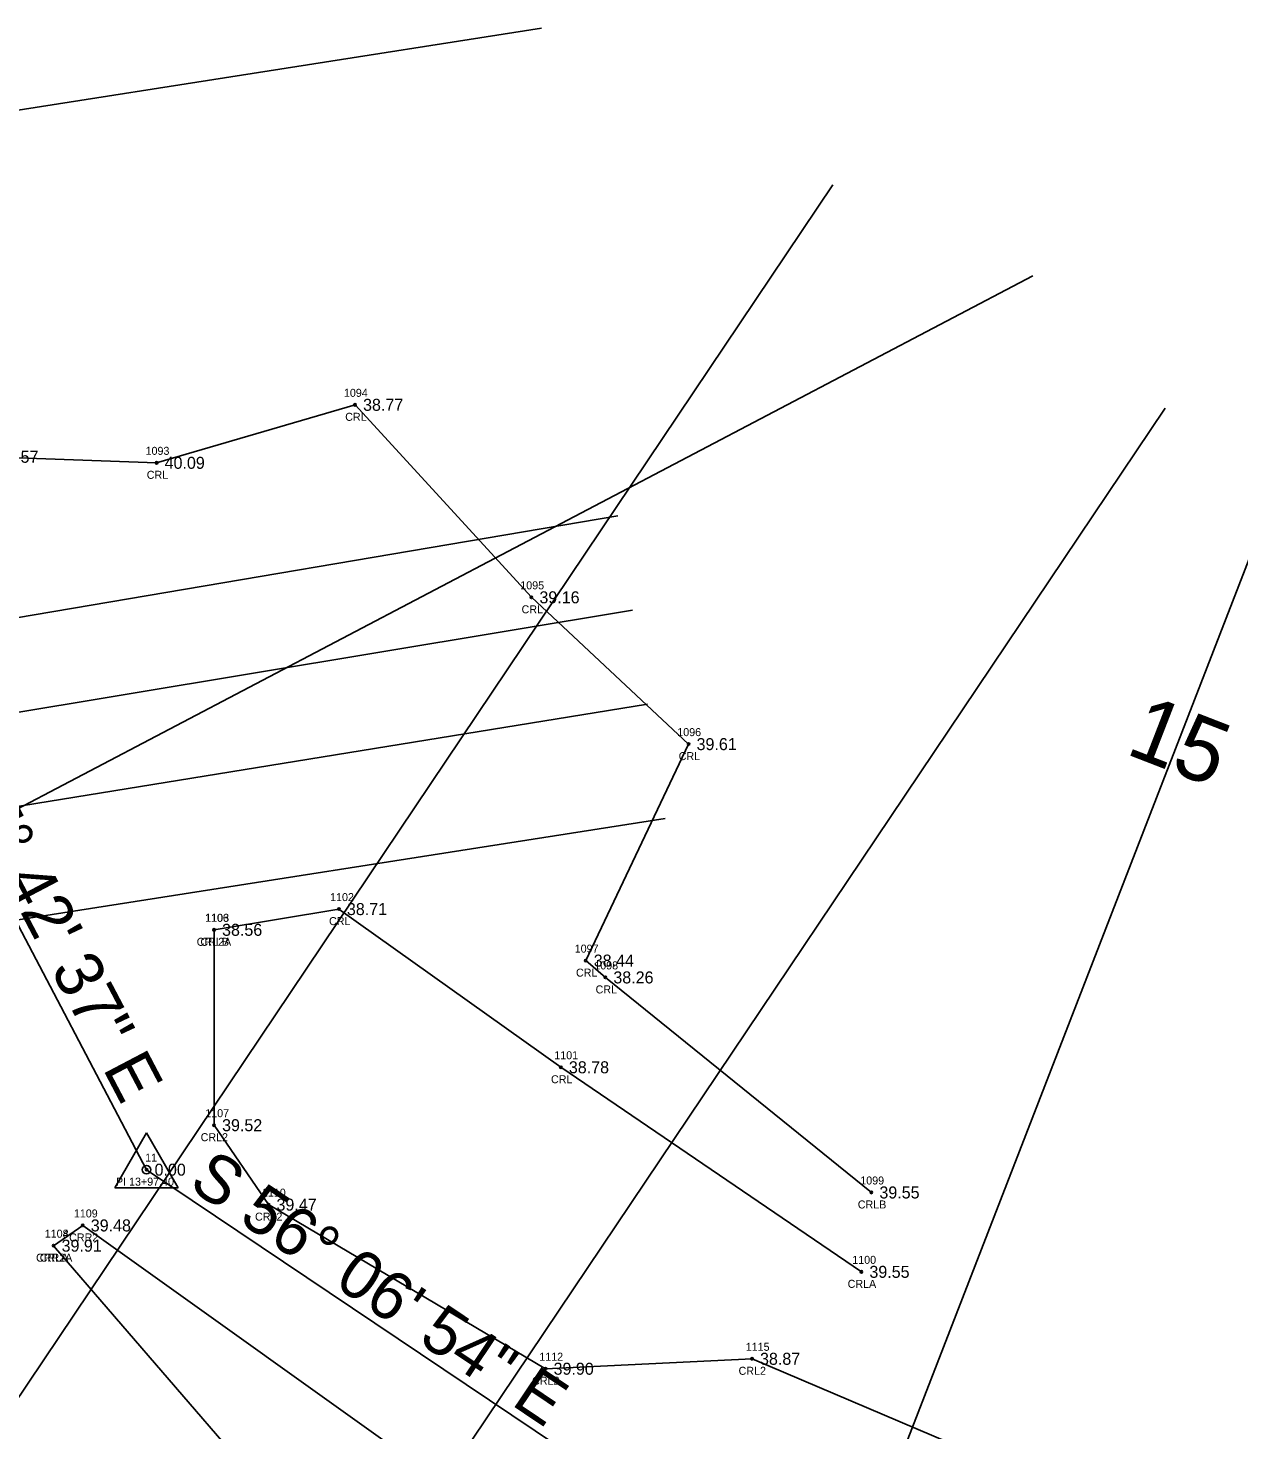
# Model space of a CAD drawing. Extents: x 2619568 to 2620316, y 784340 to 785138.
# Drawn here: x 2619908.4 to 2620059.7, y 784746.5 to 784921.7 of the extents above; entities that cross this region are included whole.
import ezdxf

# ---------------------------------------------------------------- set-up
doc = ezdxf.new("R2010")
doc.units = 0
for name, color, linetype in [('RD_EX_H2O', 7, 'Continuous'), ('RD_EX_H2O_txCode', 7, 'Continuous'), ('RD_EX_TX_H2O_ELEV', 7, 'Continuous'), ('RD_HC_Cl', 7, 'Continuous'), ('RD_HC_Data', 7, 'Continuous'), ('RD_HC_Data_Tic', 7, 'Continuous'), ('RD_HC_Survey_ELEV', 7, 'Continuous'), ('RD_HC_TX_Sta50', 7, 'Continuous'), ('RD_HC_txCode', 7, 'Continuous'), ('RD_PD_PatLn1', 7, 'Continuous'), ('RD_PD_PatLn2', 7, 'Continuous'), ('RD_PD_PatLn3', 7, 'Continuous'), ('RD_SMD_Locator', 7, 'Continuous')]:
    doc.layers.add(name, color=color, linetype=linetype)

msp = doc.modelspace()

# ---------------------------------------------------------------- linework, layer by layer
at = {"layer": 'RD_EX_H2O'}
for points in [[(2619850.74, 784850.04), (2619858.56, 784858.85), (2619863.71, 784859.84), (2619875.95, 784863.3), (2619903.67, 784868.12), (2619924.46, 784867.36), (2619949.26, 784874.61), (2619971.3, 784850.55), (2619990.94, 784832.2), (2619978.09, 784805.14), (2619980.54, 784803.04), (2620013.79, 784776.16)], [(2620012.54, 784766.24), (2619974.98, 784791.81), (2619947.24, 784811.58), (2619931.64, 784808.99)], [(2619931.64, 784808.99), (2619931.64, 784784.57), (2619938.44, 784774.64), (2619973.07, 784754.13), (2619998.87, 784755.37), (2620062.51, 784728.27), (2620105.87, 784718.88)], [(2619911.58, 784769.51), (2619915.23, 784772.04), (2619960.88, 784739.4), (2619973.19, 784724.95), (2619986.7, 784721.35)], [(2619911.58, 784769.51), (2619942.07, 784734.16), (2619962.53, 784717.9), (2619979.79, 784710.86), (2619986.7, 784721.35)]]:
    msp.add_lwpolyline(points, dxfattribs=at)
at = {"layer": 'RD_HC_Cl'}
for p, q in [((2619892.62, 784837.22), (2619923.2, 784779.01)), ((2619923.2, 784779.01), (2619981.06, 784740.15))]:
    msp.add_line(p, q, dxfattribs=at)
at = {"layer": 'RD_HC_Data'}
for p, q in [((2619919.23, 784776.72), (2619923.2, 784783.6)), ((2619923.2, 784783.6), (2619927.17, 784776.72)), ((2619919.23, 784776.72), (2619927.17, 784776.72))]:
    msp.add_line(p, q, dxfattribs=at)
msp.add_circle((2619923.2, 784779.01), 0.529, dxfattribs=at)
at = {"layer": 'RD_HC_Data_Tic'}
msp.add_line((2619925.35, 784777.56), (2619927.58, 784780.88), dxfattribs=at)
at = {"layer": 'RD_PD_PatLn1'}
for p, q in [((2619972.54, 784921.71), (2619676.16, 784875.24)), ((2619988.03, 784822.91), (2619691.65, 784776.44))]:
    msp.add_line(p, q, dxfattribs=at)
at = {"layer": 'RD_PD_PatLn2'}
for p, q in [((2620008.98, 784902.09), (2619841.72, 784653.04)), ((2620033.95, 784890.73), (2619768.36, 784751.23)), ((2620050.49, 784874.21), (2619883.23, 784625.16)), ((2620065.93, 784868.13), (2619957.53, 784588.4))]:
    msp.add_line(p, q, dxfattribs=at)
at = {"layer": 'RD_PD_PatLn3'}
for p, q in [((2619686.31, 784810.54), (2619982.1, 784860.72)), ((2619687.99, 784799.79), (2619983.95, 784848.95)), ((2619689.68, 784789.04), (2619985.79, 784837.19))]:
    msp.add_line(p, q, dxfattribs=at)
at = {"layer": 'RD_SMD_Locator'}
for centre in [(2619949.26, 784874.61), (2619924.46, 784867.36), (2619971.3, 784850.55), (2619990.94, 784832.2), (2619947.24, 784811.58), (2619931.64, 784808.99), (2619931.64, 784808.99), (2619978.09, 784805.14), (2619980.54, 784803.04), (2619974.98, 784791.81), (2619931.64, 784784.57), (2619923.2, 784779.01), (2619938.44, 784774.64), (2620013.79, 784776.16), (2619915.23, 784772.04), (2619911.58, 784769.51), (2619911.58, 784769.51), (2620012.54, 784766.24), (2619998.87, 784755.37), (2619973.07, 784754.13)]:
    msp.add_circle(centre, 0.15, dxfattribs=at)

# ---------------------------------------------------------------- texts
at = {"layer": 'RD_EX_H2O_txCode'}
for s, p in [('1094', (2619947.87, 784875.61)), ('CRL', (2619948.03, 784872.61)), ('1093', (2619923.08, 784868.36)), ('CRL', (2619923.23, 784865.36)), ('1095', (2619969.91, 784851.55)), ('CRL', (2619970.07, 784848.55)), ('1096', (2619989.53, 784833.2)), ('CRL', (2619989.71, 784830.2)), ('1102', (2619946.14, 784812.58)), ('1106', (2619930.51, 784809.99)), ('1103', (2619930.54, 784809.99)), ('CRL', (2619946.01, 784809.58)), ('CRL2A', (2619929.47, 784806.99)), ('CRLB', (2619929.94, 784806.99)), ('1097', (2619976.71, 784806.14)), ('1098', (2619979.16, 784804.04)), ('CRL', (2619976.87, 784803.14)), ('CRL', (2619979.32, 784801.04)), ('1101', (2619974.16, 784792.81)), ('CRL', (2619973.75, 784789.81)), ('1107', (2619930.54, 784785.57)), ('CRL2', (2619929.96, 784782.57)), ('1099', (2620012.4, 784777.16)), ('1110', (2619937.62, 784775.64)), ('CRLB', (2620012.09, 784774.16)), ('1109', (2619914.12, 784773.04)), ('CRL2', (2619936.76, 784772.64)), ('1104', (2619910.48, 784770.51)), ('1108', (2619910.48, 784770.51)), ('CRR2', (2619913.53, 784770.04)), ('CRR2A', (2619909.39, 784767.51)), ('CRLA', (2619909.86, 784767.51)), ('1100', (2620011.4, 784767.24)), ('CRLA', (2620010.82, 784764.24)), ('1115', (2619998.09, 784756.37)), ('1112', (2619972.29, 784755.13)), ('CRL2', (2619997.19, 784753.37)), ('CRL2', (2619971.39, 784752.13))]:
    msp.add_text(s, height=1, dxfattribs=at).set_placement(p)
at = {"layer": 'RD_EX_TX_H2O_ELEV'}
for s, p in [('38.77', (2619950.26, 784873.86)), ('39.57', (2619904.67, 784867.37)), ('40.09', (2619925.46, 784866.61)), ('39.16', (2619972.3, 784849.8)), ('39.61', (2619991.94, 784831.45)), ('38.71', (2619948.24, 784810.83)), ('38.56', (2619932.64, 784808.24)), ('38.56', (2619932.64, 784808.24)), ('38.44', (2619979.09, 784804.39)), ('38.26', (2619981.54, 784802.29)), ('38.78', (2619975.98, 784791.06)), ('39.52', (2619932.64, 784783.82)), ('39.55', (2620014.79, 784775.41)), ('39.47', (2619939.44, 784773.89)), ('39.48', (2619916.23, 784771.29)), ('39.91', (2619912.58, 784768.76)), ('39.91', (2619912.58, 784768.76)), ('39.55', (2620013.54, 784765.49)), ('38.87', (2619999.87, 784754.62)), ('39.90', (2619974.07, 784753.38))]:
    msp.add_text(s, height=1.5, dxfattribs=at).set_placement(p)
at = {"layer": 'RD_HC_Data'}
for s, rotation, p in [('S 27%%d 42\' 37" E', 297.7103, (2619895.05, 784834.74)), ('S 56%%d 06\' 54" E', 326.1149, (2619928.27, 784776.81))]:
    msp.add_text(s, height=6, rotation=rotation, dxfattribs=at).set_placement(p)
at = {"layer": 'RD_HC_Survey_ELEV'}
msp.add_text('0.00', height=1.5, dxfattribs=at).set_placement((2619924.2, 784778.26))
at = {"layer": 'RD_HC_TX_Sta50'}
msp.add_text('15', height=8, rotation=338.8179, dxfattribs=at).set_placement((2620045.39, 784831.05))
at = {"layer": 'RD_HC_txCode'}
for s, p in [('11', (2619923.03, 784780.01)), ('PI 13+97.40', (2619919.38, 784777.01))]:
    msp.add_text(s, height=1, dxfattribs=at).set_placement(p)

doc.saveas('drawing.dxf')
